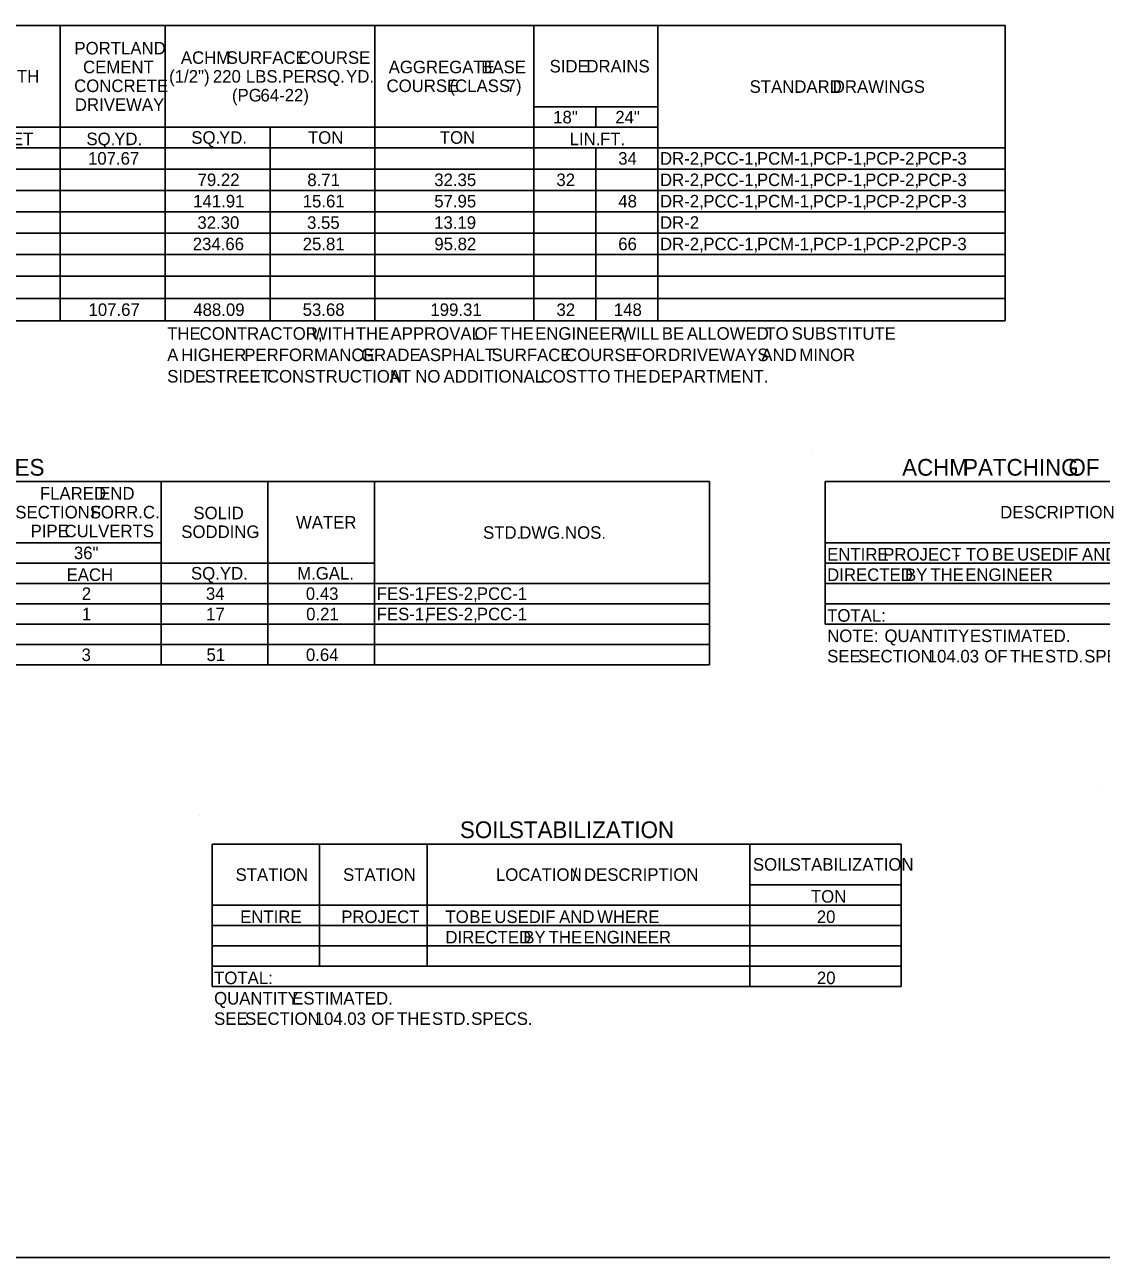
# Model space of a CAD drawing. Extents: x 3289 to 10164, y -1238 to -188.
# Drawn here: x 6334 to 6849, y -1238 to -648 of the extents above; entities that cross this region are included whole.
import ezdxf

# ---------------------------------------------------------------- set-up
doc = ezdxf.new("R2010")
doc.units = 0
for name, color, linetype in [('Default', 7, 'Continuous'), ('DSN_DRFT_Named-Boundary', 7, 'Continuous'), ('DSN_QNTY_Annotation', 7, 'Continuous')]:
    doc.layers.add(name, color=color, linetype=linetype)

msp = doc.modelspace()

# ---------------------------------------------------------------- linework, layer by layer
at = {"layer": 'DSN_DRFT_Named-Boundary'}
for p, q in [((6711.15, -852.84), (6711.15, -852.84)), ((6847.95, -1012.64), (6847.95, -1012.64)), ((6417.62, -1026.29), (6417.62, -1026.29))]:
    msp.add_line(p, q, dxfattribs=at)
msp.add_lwpolyline([(5913.57, -1237.74), (7538.57, -1237.74), (7538.57, -187.74), (5913.57, -187.74)], close=True, dxfattribs=at)
at = {"layer": 'DSN_QNTY_Annotation'}
for p, q in [((5941.78, -648.19), (6803.19, -648.19)), ((6350.79, -789.56), (6350.79, -648.19)), ((6401.01, -789.56), (6401.01, -648.19)), ((6501.43, -789.56), (6501.43, -648.19)), ((6577.48, -789.56), (6577.48, -648.19)), ((6636.96, -778.84), (6636.96, -648.19)), ((6636.96, -789.56), (6636.96, -648.19)), ((6803.19, -789.56), (6803.19, -648.19)), ((6803.19, -789.56), (6803.19, -648.19)), ((6577.48, -687.19), (6636.96, -687.19)), ((6607.22, -696.94), (6607.22, -687.19)), ((6607.22, -696.94), (6607.22, -687.19)), ((6300.58, -696.94), (6636.96, -696.94)), ((6350.79, -706.69), (6350.79, -696.94)), ((6401.01, -706.69), (6401.01, -696.94)), ((6451.22, -789.56), (6451.22, -696.94)), ((6501.43, -789.56), (6501.43, -696.94)), ((6577.48, -696.94), (6636.96, -696.94)), ((5941.78, -706.69), (6636.96, -706.69)), ((6607.22, -778.84), (6607.22, -706.69)), ((6607.22, -789.56), (6607.22, -706.69)), ((6636.96, -706.69), (6803.19, -706.69)), ((6636.96, -706.69), (6803.19, -706.69)), ((5941.78, -716.93), (6803.19, -716.93)), ((5941.78, -727.16), (6803.19, -727.16)), ((5941.78, -737.4), (6803.19, -737.4)), ((5941.78, -747.64), (6803.19, -747.64)), ((5941.78, -757.88), (6803.19, -757.88)), ((5941.78, -768.11), (6803.19, -768.11)), ((6300.58, -768.11), (6803.19, -768.11)), ((5941.78, -778.84), (6803.19, -778.84)), ((6350.79, -789.56), (6350.79, -778.84)), ((6401.01, -778.84), (6451.22, -778.84)), ((6451.22, -778.84), (6577.48, -778.84)), ((6577.48, -778.84), (6636.96, -778.84)), ((6636.96, -778.84), (6803.19, -778.84)), ((5941.78, -789.56), (6803.19, -789.56)), ((5938.54, -866.49), (6661.6, -866.49)), ((6399.13, -954.24), (6399.13, -866.49)), ((6450.22, -954.24), (6450.22, -866.49)), ((6450.22, -954.24), (6450.22, -866.49)), ((6501.31, -954.24), (6501.31, -866.49)), ((6661.6, -954.24), (6661.6, -866.49)), ((6717, -866.49), (6981.03, -866.49)), ((6717, -934.74), (6717, -866.49)), ((6717, -934.74), (6717, -866.49)), ((6218.95, -895.74), (6399.13, -895.74)), ((6399.13, -954.24), (6399.13, -895.74)), ((6717, -895.74), (6981.03, -895.74)), ((6218.95, -905.49), (6501.31, -905.49)), ((6501.31, -954.24), (6501.31, -905.49)), ((6717, -905.49), (6981.03, -905.49)), ((5938.54, -915.24), (6501.31, -915.24)), ((6501.31, -915.24), (6661.6, -915.24)), ((6501.31, -915.24), (6661.6, -915.24)), ((6661.6, -934.74), (6661.6, -915.24)), ((6717, -915.24), (6981.03, -915.24)), ((5938.54, -924.99), (6661.6, -924.99)), ((6501.31, -924.99), (6661.6, -924.99)), ((6717, -924.99), (6981.03, -924.99)), ((5938.54, -934.74), (6661.6, -934.74)), ((6717, -934.74), (6981.03, -934.74)), ((5938.54, -944.49), (6661.6, -944.49)), ((6661.6, -954.24), (6661.6, -944.49)), ((5938.54, -954.24), (6661.6, -954.24)), ((6423.47, -1039.94), (6753.41, -1039.94)), ((6423.47, -1108.19), (6423.47, -1039.94)), ((6423.47, -1108.19), (6423.47, -1039.94)), ((6474.95, -1098.44), (6474.95, -1039.94)), ((6526.43, -1098.44), (6526.43, -1039.94)), ((6680.87, -1108.19), (6680.87, -1039.94)), ((6753.41, -1108.19), (6753.41, -1039.94)), ((6753.41, -1108.19), (6753.41, -1039.94)), ((6680.87, -1059.44), (6753.41, -1059.44)), ((6423.47, -1069.19), (6753.41, -1069.19)), ((6423.47, -1069.19), (6753.41, -1069.19)), ((6474.95, -1098.44), (6474.95, -1069.19)), ((6526.43, -1098.44), (6526.43, -1069.19)), ((6680.87, -1098.44), (6680.87, -1069.19)), ((6423.47, -1078.94), (6753.41, -1078.94)), ((6423.47, -1088.69), (6753.41, -1088.69)), ((6423.47, -1098.44), (6474.95, -1098.44)), ((6423.47, -1098.44), (6753.41, -1098.44)), ((6423.47, -1108.19), (6753.41, -1108.19))]:
    msp.add_line(p, q, dxfattribs=at)

# ---------------------------------------------------------------- texts
at = {"layer": 'Default'}
for s, height, p in [('PORTLAND', 6, (6357.58, -662.06)), ('ACHM', 6, (6408.54, -666.56)), (' SURFACE', 6, (6428.21, -666.56)), (' COURSE', 6, (6462.66, -666.56)), ('CEMENT', 6, (6361.69, -671.06)), ('AGGREGATE', 6, (6508.04, -671.06)), (' BASE', 6, (6550.11, -671.06)), ('SIDE', 6, (6585.08, -670.69)), (' DRAINS', 6, (6600.46, -670.69)), ('WIDTH', 6, (6314.43, -675.56)), ('(1/2")', 6, (6402.93, -675.56)), (' 220', 6, (6421.63, -675.56)), (' LBS.', 6, (6437.43, -675.56)), (' PER', 6, (6454.9, -675.56)), (' SQ.', 6, (6471.04, -675.56)), (' YD.', 6, (6485.41, -675.56)), ('CONCRETE', 6, (6357.44, -680.06)), ('(PG', 6, (6432.99, -684.56)), (' 64-22)', 6, (6444.42, -684.56)), ('COURSE', 6, (6507.01, -680.06)), (' (CLASS', 6, (6534.93, -680.06)), (' 7)', 6, (6562.29, -680.06)), ('STANDARD', 6, (6680.84, -680.44)), (' DRAWINGS', 6, (6718.43, -680.44)), ('DRIVEWAY', 6, (6357.78, -689.06)), ('18"', 6, (6586.8, -695.06)), ('24"', 6, (6616.54, -695.06)), ('FEET', 6, (6317.37, -705.49)), ('SQ.', 6, (6363.32, -705.49)), (' YD.', 6, (6374.38, -705.49)), ('SQ.', 6, (6413.54, -704.81)), (' YD.', 6, (6424.59, -704.81)), ('TON', 6, (6469.38, -704.81)), ('TON', 6, (6532.51, -704.81)), ('LIN.', 6, (6594.7, -705.49)), (' FT.', 6, (6606.97, -705.49)), ('107.67', 6, (6364.07, -714.81)), ('34', 6, (6617.93, -714.81)), ('DR-2,', 6, (6637.93, -714.81)), (' PCC-1,', 6, (6656.45, -714.81)), (' PCM-1,', 6, (6682.11, -714.81)), (' PCP-1,', 6, (6708.92, -714.81)), (' PCP-2,', 6, (6733.92, -714.81)), (' PCP-3', 6, (6758.92, -714.81)), ('79.22', 6, (6416.56, -725.05)), ('8.71', 6, (6469.08, -725.05)), ('32.35', 6, (6529.86, -725.05)), ('32', 6, (6588.34, -725.05)), ('DR-2,', 6, (6637.93, -725.05)), (' PCC-1,', 6, (6656.45, -725.05)), (' PCM-1,', 6, (6682.11, -725.05)), (' PCP-1,', 6, (6708.92, -725.05)), (' PCP-2,', 6, (6733.92, -725.05)), (' PCP-3', 6, (6758.92, -725.05)), ('141.91', 6, (6414.43, -735.28)), ('15.61', 6, (6466.86, -735.28)), ('57.95', 6, (6529.86, -735.28)), ('48', 6, (6617.97, -735.28)), ('DR-2,', 6, (6637.93, -735.28)), (' PCC-1,', 6, (6656.45, -735.28)), (' PCM-1,', 6, (6682.11, -735.28)), (' PCP-1,', 6, (6708.92, -735.28)), (' PCP-2,', 6, (6733.92, -735.28)), (' PCP-3', 6, (6758.92, -735.28)), ('32.30', 6, (6416.44, -745.52)), ('3.55', 6, (6468.95, -745.52)), ('13.19', 6, (6529.8, -745.52)), ('DR-2', 6, (6637.93, -745.52)), ('234.66', 6, (6414.21, -755.76)), ('25.81', 6, (6466.86, -755.76)), ('95.82', 6, (6529.9, -755.76)), ('66', 6, (6617.95, -755.76)), ('DR-2,', 6, (6637.93, -755.76)), (' PCC-1,', 6, (6656.45, -755.76)), (' PCM-1,', 6, (6682.11, -755.76)), (' PCP-1,', 6, (6708.92, -755.76)), (' PCP-2,', 6, (6733.92, -755.76)), (' PCP-3', 6, (6758.92, -755.76)), ('107.67', 6, (6364.32, -787.2)), ('488.09', 6, (6414.48, -787.2)), ('53.68', 6, (6466.84, -787.2)), ('199.31', 6, (6528.01, -787.2)), ('32', 6, (6588.38, -787.2)), ('148', 6, (6615.85, -787.2)), ('THE', 6, (6401.98, -798.6)), (' CONTRACTOR,', 6, (6415.29, -798.6)), (' WITH', 6, (6468.99, -798.6)), (' THE', 6, (6490, -798.6)), (' APPROVAL', 6, (6506.71, -798.6)), (' OF', 6, (6546.88, -798.6)), (' THE', 6, (6559.22, -798.6)), (' ENGINEER,', 6, (6575.92, -798.6)), (' WILL', 6, (6616.65, -798.6)), (' BE', 6, (6636.59, -798.6)), (' ALLOWED', 6, (6648.57, -798.6)), (' TO', 6, (6686.12, -798.6)), (' SUBSTITUTE', 6, (6698.72, -798.6)), ('A', 6, (6401.98, -808.84)), (' HIGHER', 6, (6406.45, -808.84)), (' PERFORMANCE', 6, (6436.66, -808.84)), (' GRADE', 6, (6492.57, -808.84)), (' ASPHALT', 6, (6520.17, -808.84)), (' SURFACE', 6, (6555.02, -808.84)), (' COURSE', 6, (6590.26, -808.84)), (' FOR', 6, (6622.22, -808.84)), (' DRIVEWAYS', 6, (6639.55, -808.84)), (' AND', 6, (6684.23, -808.84)), (' MINOR', 6, (6702.42, -808.84)), ('SIDE', 6, (6401.98, -819.08)), (' STREET', 6, (6417.64, -819.08)), (' CONSTRUCTION', 6, (6447.52, -819.08)), (' AT', 6, (6506.22, -819.08)), (' NO', 6, (6518.51, -819.08)), (' ADDITIONAL', 6, (6532.06, -819.08)), (' COST', 6, (6578.54, -819.08)), (' TO', 6, (6600.86, -819.08)), (' THE', 6, (6613.45, -819.08)), (' DEPARTMENT.', 6, (6630.16, -819.08)), ('STRUCTURES', 8, (6270.11, -863.66)), ('ACHM', 8, (6753.87, -863.66)), (' PATCHING', 8, (6780.09, -863.66)), (' OF', 8, (6830.52, -863.66)), ('FLARED', 6, (6341.04, -875.11)), (' END', 6, (6367.19, -875.11)), ('SECTIONS', 6, (6329.27, -884.11)), (' FOR', 6, (6363.1, -884.11)), (' R.C.', 6, (6380.12, -884.11)), ('SOLID', 6, (6414.55, -884.49)), ('DESCRIPTION', 6, (6800.83, -884.11)), ('WATER', 6, (6463.64, -888.99)), ('PIPE', 6, (6336.58, -893.11)), (' CULVERTS', 6, (6350.62, -893.11)), ('SODDING', 6, (6408.73, -893.49)), ('STD.', 6, (6553.22, -893.86)), (' DWG.', 6, (6568.32, -893.86)), (' NOS.', 6, (6590.24, -893.86)), ('36"', 6, (6357.32, -903.61)), ('ENTIRE', 6, (6717.98, -904.29)), (' PROJECT', 6, (6742.58, -904.29)), (' -', 6, (6776.71, -904.29)), (' TO', 6, (6782.12, -904.29)), (' BE', 6, (6794.71, -904.29)), (' USED', 6, (6806.7, -904.29)), (' IF', 6, (6828.84, -904.29)), (' AND', 6, (6837.74, -904.29)), ('EACH', 6, (6353.81, -914.04)), ('SQ.YD.', 6, (6413.38, -913.36)), ('M.GAL.', 6, (6464.21, -913.36)), ('DIRECTED', 6, (6717.98, -914.04)), (' BY', 6, (6753.01, -914.04)), (' THE', 6, (6765.15, -914.04)), (' ENGINEER', 6, (6781.86, -914.04)), ('2', 6, (6361.08, -923.11)), ('34', 6, (6420.52, -923.11)), ('0.43', 6, (6468.36, -923.11)), ('FES-1,', 6, (6502.29, -923.11)), (' FES-2,', 6, (6523.45, -923.11)), (' PCC-1', 6, (6548.01, -923.11)), ('1', 6, (6361.17, -932.86)), ('17', 6, (6420.62, -932.86)), ('0.21', 6, (6468.52, -932.86)), ('FES-1,', 6, (6502.29, -932.86)), (' FES-2,', 6, (6523.45, -932.86)), (' PCC-1', 6, (6548.01, -932.86)), ('TOTAL:', 6, (6717.98, -933.54)), ('NOTE:', 6, (6717.98, -943.29)), ('   QUANTITY', 6, (6738.73, -943.29)), (' ESTIMATED.', 6, (6784.08, -943.29)), ('3', 6, (6360.99, -952.36)), ('51', 6, (6420.8, -952.36)), ('0.64', 6, (6468.41, -952.36)), ('SEE', 6, (6717.98, -953.04)), (' SECTION', 6, (6730.61, -953.04)), (' 104.03', 6, (6763.91, -953.04)), (' OF', 6, (6791, -953.04)), (' THE', 6, (6803.34, -953.04)), (' STD.', 6, (6820.05, -953.04)), (' SPECS.', 6, (6838.81, -953.04)), ('SOIL', 8, (6542.15, -1037.11)), (' STABILIZATION', 8, (6562.66, -1037.11)), ('SOIL', 6, (6682.42, -1052.69)), (' STABILIZATION', 6, (6697.81, -1052.69)), ('STATION', 6, (6434.72, -1057.56)), ('STATION', 6, (6486.2, -1057.56)), ('LOCATION', 6, (6559.39, -1057.56)), (' /', 6, (6593.8, -1057.56)), (' DESCRIPTION', 6, (6599.31, -1057.56)), ('TON', 6, (6710.2, -1067.99)), ('ENTIRE', 6, (6436.91, -1077.74)), ('PROJECT', 6, (6485.32, -1077.74)), ('TO', 6, (6535.21, -1077.74)), (' BE', 6, (6544.4, -1077.74)), (' USED', 6, (6556.39, -1077.74)), (' IF', 6, (6578.53, -1077.74)), (' AND', 6, (6587.43, -1077.74)), (' WHERE', 6, (6605.62, -1077.74)), ('20', 6, (6713.02, -1077.74)), ('DIRECTED', 6, (6535.21, -1087.49)), (' BY', 6, (6570.24, -1087.49)), (' THE', 6, (6582.38, -1087.49)), (' ENGINEER', 6, (6599.09, -1087.49)), ('TOTAL:', 6, (6424.45, -1106.99)), ('20', 6, (6713.06, -1106.99)), ('QUANTITY', 6, (6424.45, -1116.74)), (' ESTIMATED.', 6, (6459.59, -1116.74)), ('SEE', 6, (6424.45, -1126.49)), (' SECTION', 6, (6437.08, -1126.49)), (' 104.03', 6, (6470.38, -1126.49)), (' OF', 6, (6497.47, -1126.49)), (' THE', 6, (6509.81, -1126.49)), (' STD.', 6, (6526.52, -1126.49)), (' SPECS.', 6, (6545.28, -1126.49))]:
    msp.add_text(s, height=height, dxfattribs=at).set_placement(p)

doc.saveas('drawing.dxf')
